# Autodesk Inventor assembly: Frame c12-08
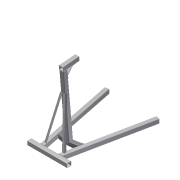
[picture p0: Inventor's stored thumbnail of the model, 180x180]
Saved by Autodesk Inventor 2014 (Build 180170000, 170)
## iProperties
Created: 2011-01
Part Number: Frame c12-08
Document SubType Name: Assembly
Designer: Thom Tremblay
_FrameDoc: Frame Assembly
_Version: 15.0.0
Author: Thom Tremblay
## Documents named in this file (20)
- C:\Inventor 2014 Essentials\Assemblies\Chapter 12\Frame\Frame c12-08.iam
- C:\Inventor 2014 Essentials\Assemblies\Chapter 12\Frame\Skeleton-c12-08.ipt
- C:\Inventor 2014 Essentials\Assemblies\Chapter 12\Frame\ANSI 3x3x3_16 00000037.ipt
- ANSI 3x3x3_16 00000037.ipt
- C:\Inventor 2014 Essentials\Assemblies\Chapter 12\Frame\ANSI 3x3x3_16 00000038.ipt
- ANSI 3x3x3_16 00000038.ipt
- C:\Inventor 2014 Essentials\Assemblies\Chapter 12\Frame\ANSI 3x3x3_16 00000039.ipt
- ANSI 3x3x3_16 00000039.ipt
- C:\Inventor 2014 Essentials\Assemblies\Chapter 12\Frame\ANSI 3x3x3_16 00000040.ipt
- ANSI 3x3x3_16 00000040.ipt
- C:\Inventor 2014 Essentials\Assemblies\Chapter 12\Frame\ANSI 3x3x3_16 00000042.ipt
- ANSI 3x3x3_16 00000042.ipt
- C:\Inventor 2014 Essentials\Assemblies\Chapter 12\Frame\ANSI 2 1_4x5_16 00000043.ipt
- ANSI 2 1_4x5_16 00000043.ipt
- C:\Inventor 2014 Essentials\Assemblies\Chapter 12\Frame\ANSI L 1.5 x 1.5 x 3_16 00000044.ipt
- ANSI L 1.5 x 1.5 x 3_16 00000044.ipt
- C:\Inventor 2014 Essentials\Assemblies\Chapter 12\Frame\ANSI L 1.5 x 1.5 x 3_16 00000045.ipt
- ANSI L 1.5 x 1.5 x 3_16 00000045.ipt
- C:\Inventor 2014 Essentials\Assemblies\Chapter 12\Frame\ANSI 3x3x3_16 00000060.ipt
- ANSI 3x3x3_16 00000060.ipt
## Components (10 placed, 10 different names)
1. Frame Reference Model
2. ANSI 3x3x3_16 00000037:1
3. ANSI 3x3x3_16 00000038:1
4. ANSI 3x3x3_16 00000039:1
5. ANSI 3x3x3_16 00000040:1
6. ANSI 3x3x3_16 00000042:1
7. ANSI 2 1_4x5_16 00000043:1
8. ANSI L 1.5 x 1.5 x 3_16 00000044:1
9. ANSI L 1.5 x 1.5 x 3_16 00000045:1
10. ANSI 3x3x3_16 00000060:1
